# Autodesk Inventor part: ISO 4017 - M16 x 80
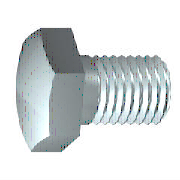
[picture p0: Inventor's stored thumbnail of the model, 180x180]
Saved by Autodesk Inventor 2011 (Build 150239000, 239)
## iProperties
IsCustomPart: 0
Created: 2010-02
Part Number: ISO 4017 - M16 x 80
Material: Stainless Steel, 440C
Description: Hexagon head screws
Document SubType Name: Modeling
Standard: ISO 4017
Designer: 129877
Standard Revision: Third edition 1999-08-15
Standards Organization: ISO
Language: en-US
Size Designation: M16 x 80
Categories: <MemberInstance><Categories><Category DisplayName="Fasteners" InternalName="e4da775c-781d-43d5-af7c-5136215cf5a6" Mnemonic="FSTN"><Category DisplayName="Bolts"
Density: 7.75 g/cm^3
Mass: 162.294 g
Surface Area: 57.7884 cm^2
Volume: 20.9411 cm^3
Author: 129877
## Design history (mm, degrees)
body "Solid1"
workplane "Work Plane1"
revolve "Body" stored, may be unused: angle "d12" = 90 deg
sketch "Sketch2"
  geometry: L1 (0, 13.856)-(12, 6.928); L2 (12, 6.928)-(12, -6.928); L3 (12, -6.928)-(0, -13.856); L4 (0, -13.856)-(-12, -6.928); L5 (-12, -6.928)-(-12, 6.928); L6 (-12, 6.928)-(0, 13.856); 2 further points
  constraints: 12 end point, 1 coincident, 1 vertical, 11 other
  dimensions: "d11" = 24 distance between parallel lines of L5 L2 (= SW)
extrude "Head" join sketch "Sketch2" distance "d3" = 9.2 (= KOH - SD); taper "d4" = 0 deg
revolve "Chamfer1" stored, may be unused: angle "d21" = 90 deg
feature "Thread" dims "d15" = 74 (= GEL), "d16" = 0
chamfer "Chamfer2" distance "d6" = 1.2269 (= -0.5 x SPD + 0.5 x GD); stored, may be unused: second distance "d7" = 1.227 (computed from GUL), angle "d55" = 45 deg
sketch "Sketch1"
  geometry: L1 (0, 11.245)-(0, 8); L2 (6, 8)-(80, 8); L3 (80, 8)-(80, 0); L4 (80, 0)-(-0.8, 0); L5 (-16.96, 0)-(96.16, 0) reference; L6 (-0.8, 0)-(-0.8, 11.245); L7 (-0.8, 11.245)-(0, 11.245); L8 (6, 8)-(4.773, 8); L9 (4.773, 8)-(0, 8); L10 (0, -2.249)-(0, 13.494) reference
  constraints: 16 end point, 2 collinear, 2 perpendicular, 1 parallel
  dimensions: "d0" = 80 distance between parallel lines of L3 L1 (= NLG); "d1" = 74 distance from line of L2.start L3 (= GEL); "d2" = 16 diameter of L2 L4 (= GD); "d9" = 0.8001 distance between parallel lines of L6 L1 (computed from SD); "d10" = 22.49 diameter of L7 L4 (= SD2); "d13" = 1.227 distance of L2.start L8.end (computed from GAL); "d14" = 16 diameter of L9 L4 (= BDM)
sketch "Sketch4"
  geometry: L1 (-10, 12)-(-10, 13.856); L2 (-10, 13.856)-(-8.928, 13.856); L3 (-8.928, 13.856)-(-10, 12); L4 (-11.84, 0)-(1.04, 0) reference; L5 (-0.8, 13.856)-(-10, 13.856) reference; L6 (-10, 6.928)-(-10, 13.856) reference
  constraints: 6 end point, 2 collinear, 1 perpendicular, 1 vertical
  dimensions: "d5" = 30 deg angle of L3 L1 (= ANG1); "d19" = 24 diameter of L1.start L4 (= SW0)
other parameters: "NLG" = 80 [user parameter; used in 1 equation term], "GD" = 16 (= NND) [user parameter; used in 2 equation terms], "BDM" = 16 (= NND) [user parameter; used in 1 equation term], "KOH" = 10 [user parameter; used in 1 equation term], "GEL" = 74 [user parameter; used in 2 equation terms], "SW" = 24 [user parameter; used in 2 equation terms], "SW0" = 24 (= SW) [user parameter; used in 1 equation term], "SPD" = 13.5462 (= NND - 1.2269 x PTC) [user parameter; used in 1 equation term], "SD2" = 22.49 [user parameter; used in 2 equation terms], "SD" = 0.8 [user parameter; used in 2 equation terms], "ANG1" = 30 deg [user parameter; used in 1 equation term], "GAL" = 1.2269 (= 0.61345 x PTC) [user parameter; used in 1 equation term], "GUL" = 1.2269 (= 0.61345 x PTC) [user parameter; used in 1 equation term], "d8" = 0, "RR" = 0.6 [user parameter], "d57" = 0, "d58" = 0, "TPU" = 5 (computed from PTC) [user parameter], "GD1" = 13.5462 (= THREADDIA - 1.2269 x PTC) [user parameter], "THREADDIA" = 16 [user parameter; used in 1 equation term], "SDH" = 22.49 (= SD2) [user parameter], "SDHG" = 6 [user parameter], "TOA" = 30 deg [user parameter], "PTC" = 2 [user parameter; used in 5 equation terms], "NND" = 16 [user parameter; used in 3 equation terms], "E0" = 27.72 [user parameter]
